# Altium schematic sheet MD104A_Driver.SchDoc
size Letter; Date: Not shown in title block; ApprovedBy: Not shown in title block; CheckedBy: Not shown in title block; Author: Not shown in title block; CompanyName: Not shown in title block; Engineer: Not shown in title block; Organization: Not shown in title block; Address1: Not shown in title block; Address2: Not shown in title block; Address3: Not shown in title block; Address4: Not shown in title block; DocumentNumber: 1; Revision: Use project parameter SCH_Rev; SheetNumber: 1; SheetTotal: 5; PageSetup: Record=PageOptions¦CenterHorizontal=True¦CenterVertical=True¦PrintScale=1.00¦XCorrection=1.00¦YCorrection=1.00¦PrintKind=0¦BorderSize=5000000¦LeftOffset=0¦BottomOffset=0¦Orientation=2¦PaperLength=1000¦PaperWidth=1000¦Scale=100¦PaperSource=15¦PrintQuality=600¦MediaType=1¦DitherType=10¦PaperKind=Letter¦PrintScaleMode=1
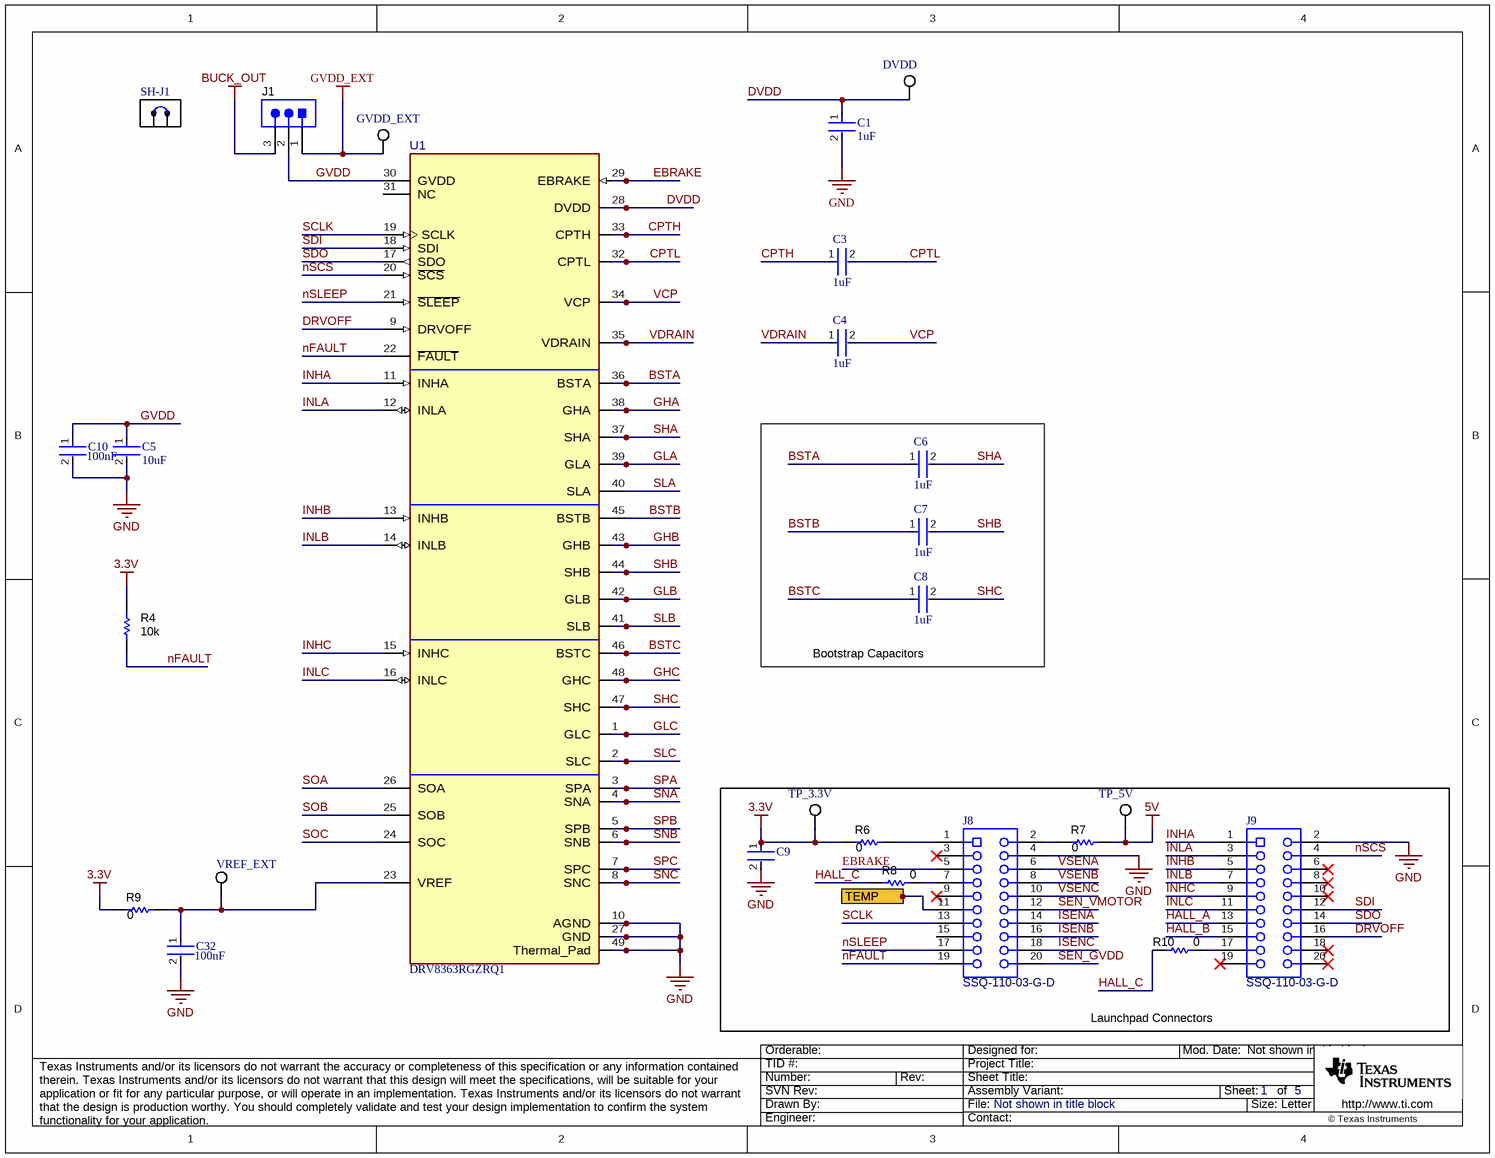
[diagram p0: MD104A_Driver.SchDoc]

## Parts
C1  1uF  [FP-GRT188-0_1-e0_2_0_5-IPC_C]
C3  1uF  [FP-GRT188-0_1-e0_2_0_5-IPC_C]
C4  1uF  [FP-GRT188-0_1-e0_2_0_5-IPC_C]
C5  10uF  [FP-GRT21B-0_2-IPC_B]
C6  1uF  [FP-GRT188-0_1-e0_2_0_5-IPC_B]
C7  1uF  [FP-GRT188-0_1-e0_2_0_5-IPC_B]
C8  1uF  [FP-GRT188-0_1-e0_2_0_5-IPC_B]
C9  GRT155R61C225KE13J  [FP-GRT155-0_2-IPC_A]  (value not drawn)
C10  Capacitance: 100nF  [FP-GCM155-0_05-IPC_B]  (hidden comment: GCM155R71E104KE02D)
C32  Capacitance: 100nF  [FP-GCM155-0_05-IPC_A]  (hidden comment: GCM155R71C104KA55J)
DVDD  5015  [Testpoint_Keystone_Miniature]  (value not drawn)
GVDD_EXT  5015  [Testpoint_Keystone_Miniature]  (value not drawn)
J1  61300311121  [WURTH_61300311121]  (value not drawn)
J8  SSQ-110-03-G-D  [Samtec_SSQ-110-03-x-D]
J9  SSQ-110-03-G-D  [Samtec_SSQ-110-03-x-D]
R4  value 10k  [0603L]  (hidden comment: CRCW060310K0JNEA)
R6  ValueDisplayed: 0  [0603L]  (hidden comment: RCS06030000Z0EA)
R7  ValueDisplayed: 0  [0603L]  (hidden comment: RCS06030000Z0EA)
R8  ValueDisplayed: 0  [0603L]  (hidden comment: RCS06030000Z0EA)
R9  ValueDisplayed: 0  [0603L]  (hidden comment: RCS06030000Z0EA)
R10  ValueDisplayed: 0  [0603L]  (hidden comment: RCS06030000Z0EA)
SH-J1  SNT-100-BK-G  [SNT-100-BK-G]  (value not drawn)
TP_3.3V  5015  [Testpoint_Keystone_Miniature]  (value not drawn)
TP_5V  5015  [Testpoint_Keystone_Miniature]  (value not drawn)
U1  DRV8363RGZRQ1  [RGZ0048L-MFG]
VREF_EXT  5015  [Testpoint_Keystone_Miniature]  (value not drawn)

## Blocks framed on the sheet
Bootstrap Capacitors: C6-C8
Launchpad Connectors: C9 J8 J9 R6-R8 R10 TP_3.3V TP_5V

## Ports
TEMP (out)

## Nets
3.3V: C9.1 R4.1 R6.1 R9.1 TP_3.3V.1
5V: R7.2 TP_5V.1
BUCK_OUT: J1.3
GND: C1.2 C5.2 C9.2 C10.2 C32.2 J8.4 J9.2 U1.10(AGND) U1.27(GND) U1.49(Thermal_Pad)
GVDD_EXT: GVDD_EXT.1 J1.1
BSTA: C6.1 U1.36(BSTA)
BSTB: C7.1 U1.45(BSTB)
BSTC: C8.1 U1.46(BSTC)
CPTH: C3.1 U1.33(CPTH)
CPTL: C3.2 U1.32(CPTL)
DRVOFF: J9.16 U1.9(DRVOFF)
DVDD: C1.1 DVDD.1 U1.28(DVDD)
EBRAKE: J8.5 U1.29(EBRAKE)
GHA: U1.38(GHA)
GHB: U1.43(GHB)
GHC: U1.48(GHC)
GLA: U1.39(GLA)
GLB: U1.42(GLB)
GLC: U1.1(GLC)
GVDD: C5.1 C10.1 J1.2 U1.30(GVDD)
HALL_A: J9.13
HALL_B: J9.15
HALL_C: R8.1 R10.1
INHA: J9.1 U1.11(INHA)
INHB: J9.5 U1.13(INHB)
INHC: J9.9 U1.15(INHC)
INLA: J9.3 U1.12(INLA)
INLB: J9.7 U1.14(INLB)
INLC: J9.11 U1.16(INLC)
ISENA: J8.14
ISENB: J8.16
ISENC: J8.18
nFAULT: J8.19 R4.2 U1.22(~{FAULT})
nSCS: J9.4 U1.20(~{SCS})
nSLEEP: J8.17 U1.21(~{SLEEP})
SCLK: J8.13 U1.19(SCLK)
SDI: J9.12 U1.18(SDI)
SDO: J9.14 U1.17(SDO)
SEN_GVDD: J8.20
SEN_VMOTOR: J8.12
SHA: C6.2 U1.37(SHA)
SHB: C7.2 U1.44(SHB)
SHC: C8.2 U1.47(SHC)
SLA: U1.40(SLA)
SLB: U1.41(SLB)
SLC: U1.2(SLC)
SNA: U1.4(SNA)
SNB: U1.6(SNB)
SNC: U1.8(SNC)
SOA: U1.26(SOA)
SOB: U1.25(SOB)
SOC: U1.24(SOC)
SPA: U1.3(SPA)
SPB: U1.5(SPB)
SPC: U1.7(SPC)
TEMP: J8.11 ; port TEMP
VCP: C4.2 U1.34(VCP)
VDRAIN: C4.1 U1.35(VDRAIN)
VSENA: J8.6
VSENB: J8.8
VSENC: J8.10
NetC32_1: C32.1 R9.2 U1.23(VREF) VREF_EXT.1
NetJ8_1: J8.1 R6.2
NetJ8_2: J8.2 R7.1
NetJ8_7: J8.7 R8.2
NetJ9_17: J9.17 R10.2

Not connected (* = marked no-connect by the designer): J8 3* 9* 15; J9 6* 8* 10* 18* 19* 20*; U1 31(NC)

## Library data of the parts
C1 C3 C4 C6-C8 = CMP-06035-050353-1: Multi-Layer Ceramic Capacitor 1uF 25V X7R ±10% 0603 Paper T/R GRT188R71E105KE13D
C5 = CMP-06035-008164-1: Multi-Layer Ceramic Capacitor 10uF 25V X7S ±10% 0805 Emboss T/R GRT21BC71E106KE13L
C9 = CMP-06035-019999-1: Multi-Layer Ceramic Capacitor 2.2uF 16V X5R ±10% 0402 Paper T/R GRT155R61C225KE13J
C10 = CMP-06035-054272-1: Ceramic Capacitor for Automotive 100nF ±10% 25VDC X7R 0402 Paper T/R; Voltage Rating: 25V
C32 = CMP-2008-03712-2: Ceramic Capacitor for Automotive 100nF ±10% 16VDC X7R 0402 Paper T/R GCM155R71C104KA55J; Voltage Rating: 16V
DVDD GVDD_EXT TP_3.3V TP_5V VREF_EXT = CMP-0055152-2: Test Point, Miniature, SMT; Manufacturer: Keystone Electronics; CT: TRUE; Green_Lifecycle: Active; Green_REACh: Passed; CNHeader: FALSE
J1 = CMP-0054796-4: Header, 2.54 mm, 3x1, Gold, TH; Manufacturer: Wurth Elektronik; Green_Lifecycle: Active; Green_REACh: Passed; CNHeader: TRUE; CT: FALSE
J8 J9 = CMP-0075613-1: Receptacle, 2.54mm, 10x2, Gold, TH; Manufacturer: Samtec; Pitch_mm: 2.54; Cert_VDE: N; Gender: Female; Cert_CSA: Y; Current_A: 6.3A; Voltage_V: 550V; CT: True; Row_Count: 2; CompType: Socket Strip; CNHeader: False
R4 = CMP-0025701-4: RES, 10 k, 5%, 0.1 W, AEC-Q200 Grade 0, 0603; Manufacturer: Vishay-Dale; Value_Code: 10k0; Power_W: 100mW; Value2: 0.1W; VDC_V: 75V; TempCo: 200 ppm/C; EIA_Code: E24; AEC Category: Q200; AEC Qualified: Y; AEC Grade: 0; SizeArea_mm2: 1.28; SizeX_mm: 1.6; SizeY_mm: 0.8; SizeZ_mm: 1
R6-R10 = CMP-0081973-1: RES, 0, 0%, 0.25 W, AEC-Q200 Grade 0, 0603; Manufacturer: Vishay-Dale; SizeAreaWB_mm2: 4.68; SizeArea_mm2: 1.28; AEC Qualified: Y; AEC Category: Q200; Value: 0; SizeZ_mm: 1; SizeY_mm: 0.8; Power_W: 250mW; Value2: 0.25W; SizeX_mm: 1.6
SH-J1 = CMP-0003623-3: Shunt, 100mil, Gold plated, Black; Alternate PartNumber: 969102-0000-DA; Manufacturer: Samtec; Alternate Manufacturer: 3M; Value: 1x2
U1 = CMP-0122985-1: 48V Battery Three-Phase Smart Gate Driver with Accurate Current Sensing and Advanced Monitoring; Manufacturer: Texas Instruments; SizeZ_mm: 1mm; AEC Qualified: Yes; AEC Grade: Grade 1; Max Supply Voltage: 85V; Min Supply Voltage: 8V; Number Of Drivers: 3; Propagation Delay: 42ns; Standoff Height: 0mm; TaMax_C: +125°C; TaMin_C: -40°C; TJmax_C: +150°C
